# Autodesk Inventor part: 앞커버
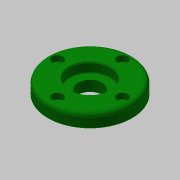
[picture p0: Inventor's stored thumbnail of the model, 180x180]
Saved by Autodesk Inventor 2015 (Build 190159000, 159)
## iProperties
Created: 2015-09
Part Number: 앞커버
Material: 알루미늄 6061
Document SubType Name: Modeling
Designer: mduedu
Density: 1 g/cm^3
Appearance: 진녹색
Author: mduedu
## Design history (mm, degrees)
sketch "스케치1"
  geometry: L1 (0, 7.5)-(0, -7.5); L2 (0, 7.5)-(31, 7.5); L3 (31, 7.5)-(31, -2.5); L4 (31, -2.5)-(17.5, -2.5); L5 (17.5, -2.5)-(17.5, -7.5); L6 (17.5, -7.5)-(0, -7.5); 2 further points
  constraints: 12 end point, 2 parallel, 2 perpendicular, 1 coincident, 1 horizontal, 1 midpoint, 1 vertical
  dimensions: "d0" = 15 distance of L1.start L1.end; "d1" = 62 diameter of L3 L1; "d2" = 35 diameter of L5 L1; "d3" = 10 distance of L2.end L3.end
revolve "회전1" sketch "스케치1" stored, may be unused: angle "d4" = 90 deg
hole "구멍1" diameter "d7" = 30; stored, may be unused: countersink angle "d11" = 90 deg, drill point angle "d13" = 0 deg; dims "d8" = 6, "d9" = 4, "d10" = 2, "d12" = 7.3, "d46" = 10, "d47" = 10
hole "구멍2" diameter "d16" = 18; stored, may be unused: countersink angle "d20" = 90 deg, drill point angle "d22" = 0 deg; dims "d14" = 10, "d15" = 10, "d17" = 6, "d18" = 4, "d19" = 2, "d21" = 7.3
fillet "모깎기2" dims "d48" = 3
chamfer "모따기2" distance "d26" = 0.7; stored, may be unused: second distance "d27" = 2, angle "d28" = 30 deg
fillet "모깎기1" dims "d29" = 0.3
sketch "스케치4" dims "d49" = 48
  geometry: 3 further points
  constraints: 2 vertical alignment, 1 coincident, 2 other
hole "구멍4" sketch "스케치4" at (0, 24) diameter "d50" = 4.5; stored, may be unused: countersink angle "d54" = 90 deg, drill point angle "d56" = 118 deg; dims "d51" = 6, "d52" = 8, "d53" = 4.4, "d55" = 8
chamfer "모따기3" distance "d43" = 1; stored, may be unused: second distance "d44" = 2, angle "d45" = 45 deg
node "솔리드1"
pattern_circular "원형 패턴1" dims angle "d58" = 360 deg
